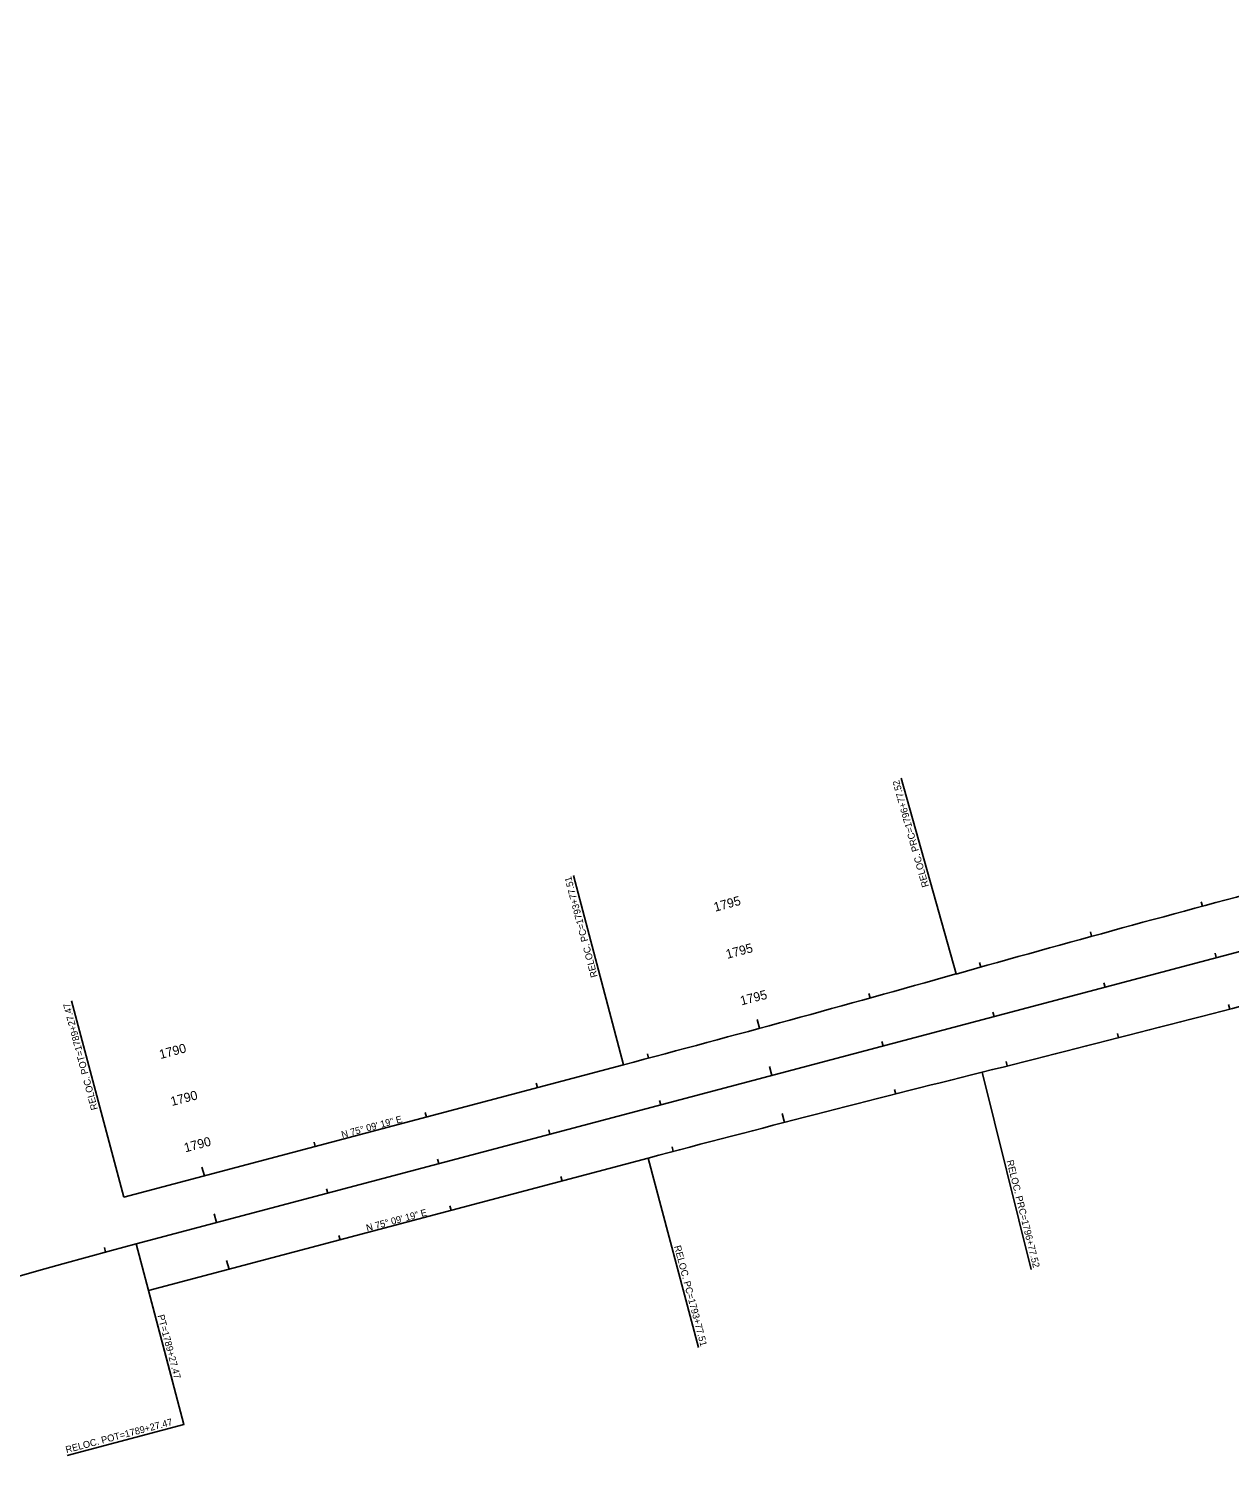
# Model space of a CAD drawing. Extents: x 2106154 to 2121963, y 864504 to 868517.
# Drawn here: x 2109996 to 2111041, y 866945 to 868210 of the extents above; entities that cross this region are included whole.
import ezdxf

# ---------------------------------------------------------------- set-up
doc = ezdxf.new("R2010")
doc.units = 0
for name, color, linetype in [('RD_HC_Cl', 7, 'Continuous'), ('RD_HC_CL_Rel', 7, 'Continuous'), ('RD_HC_Data', 7, 'Continuous'), ('RD_HC_Data_Rel', 7, 'Continuous'), ('RD_HC_Data_Tic', 7, 'Continuous'), ('RD_HC_Data_Tic_Rel', 7, 'Continuous'), ('RD_HC_TX_Rel_Sta50', 7, 'Continuous'), ('RD_HC_TX_Sta50', 7, 'Continuous'), ('RD_Sketch1', 7, 'Continuous')]:
    doc.layers.add(name, color=color, linetype=linetype)

msp = doc.modelspace()

# ---------------------------------------------------------------- linework, layer by layer
at = {"layer": 'RD_HC_Cl'}
msp.add_line((2110088.7, 867152.7), (2114077.7, 868210), dxfattribs=at)
msp.add_arc((2111556.6, 861614.4), 5729.6, 104.84478, 132.83574, dxfattribs=at)
at = {"layer": 'RD_HC_CL_Rel'}
for p, q in [((2110077.9, 867193.3), (2110513, 867308.6)), ((2110099.5, 867112.1), (2110534.5, 867227.4))]:
    msp.add_line(p, q, dxfattribs=at)
for centre, start, end in [((2116215.8, 848134.2), 104.84478, 105.70423), ((2105388.9, 886641.1), 284.84478, 285.70423), ((2105991.6, 886709.3), 283.98534, 284.84478), ((2115658.5, 847895), 103.98534, 104.84478)]:
    msp.add_arc(centre, 20000, start, end, dxfattribs=at)
at = {"layer": 'RD_HC_Data'}
msp.add_line((2110088.7, 867152.7), (2110120.7, 867032.1), dxfattribs=at)
at = {"layer": 'RD_HC_Data_Rel'}
for p, q in [((2110802.4, 867387.7), (2110754.5, 867558)), ((2110513, 867308.6), (2110469.3, 867473.3)), ((2110077.9, 867193.3), (2110032.6, 867364.4)), ((2110825, 867302.1), (2110867.8, 867130.4)), ((2110534.5, 867227.4), (2110578.1, 867062.7))]:
    msp.add_line(p, q, dxfattribs=at)
msp.add_lwpolyline([(2110099.5, 867112.1), (2110130.3, 866995.6), (2110028.7, 866968.7)], dxfattribs=at)
at = {"layer": 'RD_HC_Data_Tic'}
for p, q in [((2111028.8, 867401.9), (2111027.8, 867405.8)), ((2110932.1, 867376.3), (2110931.1, 867380.1)), ((2110835.5, 867350.7), (2110834.4, 867354.5)), ((2110738.8, 867325), (2110737.8, 867328.9)), ((2110642.1, 867299.4), (2110640.1, 867307.1)), ((2110545.5, 867273.8), (2110544.4, 867277.7)), ((2110448.8, 867248.2), (2110447.8, 867252)), ((2110352.1, 867222.6), (2110351.1, 867226.4)), ((2110255.5, 867196.9), (2110254.5, 867200.8)), ((2110158.8, 867171.3), (2110156.8, 867179)), ((2110062.2, 867145.6), (2110061.1, 867149.5))]:
    msp.add_line(p, q, dxfattribs=at)
at = {"layer": 'RD_HC_Data_Tic_Rel'}
for p, q in [((2111016.9, 867446.7), (2111015.8, 867450.6)), ((2110920.4, 867420.5), (2110919.3, 867424.3)), ((2110824, 867393.7), (2110822.9, 867397.6)), ((2110727.7, 867366.8), (2110726.6, 867370.7)), ((2111040.6, 867357.1), (2111039.6, 867361)), ((2110631.3, 867340.4), (2110629.2, 867348.1)), ((2110943.8, 867332.1), (2110942.8, 867336)), ((2110534.7, 867314.4), (2110533.7, 867318.3)), ((2110846.9, 867307.6), (2110845.9, 867311.4)), ((2110438, 867288.8), (2110437, 867292.6)), ((2110749.9, 867283.2), (2110748.9, 867287.1)), ((2110341.4, 867263.2), (2110340.4, 867267)), ((2110653, 867258.5), (2110651, 867266.2)), ((2110244.7, 867237.5), (2110243.7, 867241.4)), ((2110556.2, 867233.2), (2110555.2, 867237.1)), ((2110148.1, 867211.9), (2110146, 867219.6)), ((2110459.6, 867207.6), (2110458.5, 867211.4)), ((2110362.9, 867182), (2110361.9, 867185.8)), ((2110266.2, 867156.3), (2110265.2, 867160.2)), ((2110169.6, 867130.7), (2110167.5, 867138.4))]:
    msp.add_line(p, q, dxfattribs=at)
at = {"layer": 'RD_Sketch1'}
for p, q in [((2110127.5, 867006.5), (2110130.3, 866995.6)), ((2110130.3, 866995.6), (2110028.7, 866968.7))]:
    msp.add_line(p, q, dxfattribs=at)

# ---------------------------------------------------------------- texts
at = {"layer": 'RD_HC_Data'}
msp.add_text('PT=1789+27.47', height=6, rotation=284.8448, dxfattribs=at).set_placement((2110107.3, 867090.4))
at = {"layer": 'RD_HC_Data_Rel'}
for s, rotation, p in [('RELOC. PRC=1796+77.52', 105.7042, (2110778.8, 867464.1)), ('RELOC. PC=1793+77.51', 104.8448, (2110490.5, 867385.5)), ('RELOC. POT=1789+27.47', 104.8448, (2110055.5, 867270.1)), ('N 75%%d 09\' 19" E', 14.8448, (2110268.2, 867244.8)), ('RELOC. PRC=1796+77.52', 283.9853, (2110846.3, 867225)), ('N 75%%d 09\' 19" E', 14.8448, (2110289.8, 867163.6)), ('RELOC. PC=1793+77.51', 284.8448, (2110556.9, 867150.6)), ('RELOC. POT=1789+27.47', 14.8448, (2110028.2, 866970.6))]:
    msp.add_text(s, height=6, rotation=rotation, dxfattribs=at).set_placement(p)
at = {"layer": 'RD_HC_TX_Rel_Sta50'}
for s, rotation, p in [('1795', 15.1957, (2110592.7, 867441.8)), ('1795', 14.4939, (2110615.6, 867360.3)), ('1790', 14.8448, (2110110, 867313.6)), ('1790', 14.8448, (2110131.6, 867232.4))]:
    msp.add_text(s, height=8, rotation=rotation, dxfattribs=at).set_placement(p)
at = {"layer": 'RD_HC_TX_Sta50'}
for s, p in [('1795', (2110603.2, 867400.8)), ('1790', (2110119.9, 867272.7))]:
    msp.add_text(s, height=8, rotation=14.8448, dxfattribs=at).set_placement(p)

doc.saveas('drawing.dxf')
